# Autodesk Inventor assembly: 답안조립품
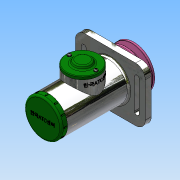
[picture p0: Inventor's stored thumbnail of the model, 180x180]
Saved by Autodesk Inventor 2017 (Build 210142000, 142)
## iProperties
Part Number: 답안조립품
Material: 일반
Document SubType Name: Assembly
Designer: user
Author: user
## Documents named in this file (20)
- C:\Users\user\Desktop\710706V1027\답안조립품.iam
- C:\Users\user\Desktop\710706V1027\본체.ipt
- C:\Users\user\Desktop\710706V1027\축.ipt
- C:\Users\user\Desktop\710706V1027\키 4 x 4 x 18.ipt
- C:\Users\user\Desktop\710706V1027\베어링 15 x 35 x 11.ipt
- C:\Users\user\Desktop\710706V1027\부시1.ipt
- C:\Users\user\Desktop\710706V1027\멈춤링 15 x 1.ipt
- C:\Users\user\Desktop\710706V1027\멈춤링 35 x 1.6.ipt
- C:\Users\user\Desktop\710706V1027\부시2.ipt
- C:\Users\user\Desktop\710706V1027\와셔 10 x 21.ipt
- C:\Users\user\Desktop\710706V1027\너트 M10.ipt
- C:\Users\user\Desktop\710706V1027\사이드 커버.ipt
- 사이드 커버.ipt
- C:\Users\user\Desktop\710706V1027\오일 실 15 25 7.ipt
- C:\Users\user\Desktop\710706V1027\탑 커버.ipt
- C:\Users\user\Desktop\710706V1027\V-벨트풀리.ipt
- C:\Users\user\Desktop\710706V1027\와셔 4 x 16.ipt
- C:\Users\user\Desktop\710706V1027\볼트 M4 x 10.ipt
- C:\Users\user\Desktop\710706V1027\와셔 3 x 6.ipt
- C:\Users\user\Desktop\710706V1027\십자볼트 M3 x 10.ipt
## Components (2 placed, 2 different names)
1. V-벨트풀리:1
2. ISO 4017 M4 x 10:1
